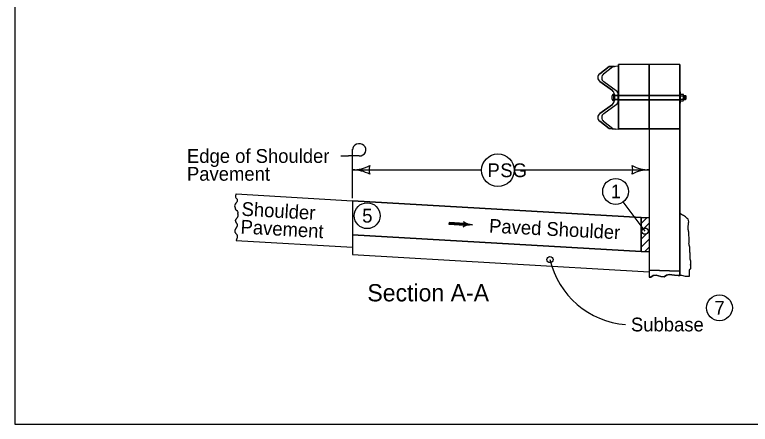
# Model space of a CAD drawing. Extents: x 6410 to 81668, y 3928 to 11667.
# Drawn here: x 6410 to 7264, y 8314 to 8790 of the extents above; entities that cross this region are included whole.
import ezdxf

# ---------------------------------------------------------------- set-up
doc = ezdxf.new("R2010")
doc.units = 0
for name, color, linetype in [('dsnNonPlotable', 7, 'Continuous'), ('dsnStdBlockModified', 7, 'Continuous'), ('dsnStdLabel', 7, 'Continuous'), ('dsnStdSection', 7, 'Continuous'), ('Level 11', 7, 'Continuous'), ('Level 14', 7, 'Continuous'), ('Level 3', 7, 'Continuous'), ('Level 7', 7, 'Continuous')]:
    doc.layers.add(name, color=color, linetype=linetype)

msp = doc.modelspace()

# ---------------------------------------------------------------- linework, layer by layer
at = {"layer": 'dsnNonPlotable'}
for p, q in [((6410.45, 9924.36), (6410.45, 8314.36)), ((6410.45, 8314.36), (9506.14, 8314.36))]:
    msp.add_line(p, q, dxfattribs=at)
at = {"layer": 'dsnStdBlockModified'}
for p, q in [((7182.32, 8731.84), (7111.23, 8731.84)), ((7111.23, 8657.19), (7111.23, 8731.84)), ((7146.78, 8657.19), (7146.78, 8731.84)), ((7182.32, 8731.84), (7182.32, 8486.8)), ((7089.29, 8721.08), (7100.05, 8729.48)), ((7093.72, 8720.85), (7104.5, 8729.26)), ((7100.05, 8729.48), (7106.38, 8729.59)), ((7104.5, 8729.26), (7110.83, 8730.38)), ((7103.99, 8701.54), (7089.48, 8711.96)), ((7108.47, 8701.31), (7093.9, 8711.76)), ((7105.62, 8689.44), (7105.62, 8697.52)), ((7182.32, 8700.14), (7183, 8700.14)), ((7183, 8686.8), (7183, 8700.14)), ((7105.62, 8695.83), (7111.04, 8695.83)), ((7105.62, 8691.17), (7111.23, 8691.17)), ((7106.39, 8690.1), (7106.39, 8696.91)), ((7106.39, 8690.1), (7106.39, 8693.51)), ((7106.39, 8693.51), (7106.39, 8690.1)), ((7106.56, 8695.83), (7111.23, 8695.83)), ((7110.83, 8693.29), (7110.83, 8696.69)), ((7110.83, 8689.88), (7110.83, 8693.29)), ((7110.83, 8693.29), (7110.83, 8689.88)), ((7111.22, 8690.83), (7182.32, 8690.83)), ((7111.23, 8696.17), (7182.32, 8696.17)), ((7111.23, 8695.83), (7182.32, 8695.83)), ((7111.23, 8691.17), (7182.32, 8691.17)), ((7183, 8697.51), (7185.97, 8697.51)), ((7183, 8695.49), (7185.97, 8695.49)), ((7183, 8691.45), (7185.97, 8691.45)), ((7183, 8689.43), (7185.97, 8689.43)), ((7186.34, 8690.44), (7186.34, 8696.5)), ((7186.34, 8695.8), (7188.71, 8695.8)), ((7186.34, 8691.14), (7188.71, 8691.14)), ((7187.23, 8695.8), (7187.23, 8691.14)), ((7187.97, 8695.8), (7187.97, 8691.14)), ((7188.71, 8695.8), (7189.15, 8695.27)), ((7188.71, 8695.8), (7188.71, 8691.14)), ((7189.15, 8691.67), (7188.71, 8691.14)), ((7189.15, 8695.27), (7189.15, 8691.67)), ((7089.48, 8675.05), (7103.99, 8685.47)), ((7093.9, 8674.82), (7108.47, 8685.27)), ((7182.32, 8686.8), (7183, 8686.8)), ((7100.05, 8657.54), (7089.29, 8665.93)), ((7104.5, 8657.32), (7093.72, 8665.73)), ((7107.16, 8656.85), (7100.05, 8657.54)), ((7110.83, 8656.2), (7104.5, 8657.32)), ((7146.78, 8657.19), (7111.23, 8657.19)), ((7146.78, 8657.19), (7146.78, 8484.96)), ((6667.24, 8581.57), (6802.39, 8573.71)), ((6802.39, 8573.71), (6802.39, 8519.7)), ((6802.39, 8573.71), (7137.52, 8554.23)), ((7137.52, 8547.48), (7144.27, 8554.23)), ((7137.52, 8547.48), (7144.27, 8554.23)), ((7137.52, 8547.48), (7144.27, 8554.23)), ((7137.52, 8547.48), (7144.27, 8554.23)), ((7137.52, 8554.23), (7146.76, 8554.23)), ((7137.52, 8554.23), (7137.52, 8514.8)), ((7137.52, 8538.3), (7146.76, 8547.53)), ((7137.52, 8538.3), (7146.76, 8547.53)), ((7137.52, 8538.3), (7146.76, 8547.53)), ((7137.52, 8538.3), (7146.76, 8547.53)), ((7192.37, 8547.46), (7192.37, 8547.46)), ((7137.52, 8529.07), (7146.76, 8538.31)), ((7137.52, 8529.07), (7146.76, 8538.31)), ((7137.52, 8529.07), (7146.76, 8538.31)), ((7137.52, 8529.07), (7146.76, 8538.31)), ((6667.28, 8527.56), (6802.39, 8519.7)), ((7137.52, 8514.8), (6802.39, 8534.12)), ((7137.52, 8519.84), (7146.76, 8529.08)), ((6802.39, 8519.7), (6802.39, 8511.28)), ((7141.62, 8514.8), (7146.76, 8519.94)), ((6802.39, 8511.28), (7146.78, 8491.42)), ((7137.52, 8514.8), (7146.76, 8514.8))]:
    msp.add_line(p, q, dxfattribs=at)
for points in [[(7186.32, 8690.76), (7186.28, 8691.03), (7186.23, 8691.2), (7186.14, 8691.36), (7186.02, 8691.45), (7186.1, 8691.55), (7186.18, 8691.77), (7186.24, 8692.08), (7186.32, 8692.83), (7186.32, 8690.76), (7186.3, 8690.9), (7186.26, 8691.12), (7186.18, 8691.33), (7186.07, 8691.44), (7186.1, 8691.53), (7186.16, 8691.68), (7186.27, 8692.18), (7186.31, 8692.56), (7186.3, 8690.95), (7186.28, 8691.07), (7186.23, 8691.24), (7186.1, 8691.44), (7186.16, 8691.61), (7186.23, 8691.94), (7186.29, 8692.27), (7186.28, 8691.11), (7186.24, 8691.24), (7186.13, 8691.43), (7186.17, 8691.65), (7186.23, 8691.9), (7186.27, 8692.08), (7186.26, 8691.21), (7186.2, 8691.32), (7186.16, 8691.43), (7186.24, 8691.89), (7186.24, 8691.29), (7186.17, 8691.43), (7186.22, 8691.72), (7186.22, 8691.37), (7186.19, 8691.44), (7186.2, 8691.54), (7186.2, 8691.46)], [(7186.03, 8695.49), (7186.11, 8695.54), (7186.18, 8695.64), (7186.26, 8695.86), (7186.32, 8696.15), (7186.32, 8694.2), (7186.26, 8694.71), (7186.21, 8695.08), (7186.09, 8695.41), (7186.04, 8695.49), (7186.09, 8695.5), (7186.2, 8695.65), (7186.28, 8695.87), (7186.3, 8696.03), (7186.31, 8694.49), (7186.23, 8694.98), (7186.18, 8695.25), (7186.07, 8695.47), (7186.1, 8695.48), (7186.24, 8695.7), (7186.28, 8695.85), (7186.29, 8694.75), (7186.1, 8695.46), (7186.26, 8695.74), (7186.27, 8694.88), (7186.12, 8695.45), (7186.24, 8695.67), (7186.25, 8695.03), (7186.14, 8695.43), (7186.23, 8695.6), (7186.23, 8695.19), (7186.16, 8695.42), (7186.21, 8695.53), (7186.21, 8695.33), (7186.18, 8695.4), (7186.19, 8695.45)], [(7192.84, 8523.62), (7192.78, 8523.35), (7192.78, 8523.15), (7192.78, 8522.95), (7192.78, 8522.76), (7192.78, 8522.56), (7192.78, 8522.37), (7192.78, 8522.08), (7192.78, 8521.88), (7192.88, 8521.59), (7192.98, 8521.29), (7193.17, 8521.1), (7193.17, 8520.9), (7193.27, 8520.71), (7193.27, 8520.51), (7193.27, 8520.32), (7193.37, 8520.22), (7193.37, 8520.02), (7193.37, 8519.83), (7193.37, 8519.63), (7193.37, 8519.44), (7193.37, 8519.24), (7193.37, 8518.95), (7193.37, 8518.66), (7193.37, 8518.46), (7193.37, 8518.17), (7193.37, 8517.97), (7193.37, 8517.78), (7193.47, 8517.68), (7193.47, 8517.48), (7193.47, 8517.29), (7193.47, 8517.09), (7193.47, 8516.9), (7193.47, 8516.7), (7193.47, 8516.51), (7193.47, 8516.31), (7193.47, 8516.12), (7193.47, 8515.92), (7193.47, 8515.72), (7193.47, 8515.53), (7193.47, 8515.33), (7193.47, 8515.14), (7193.47, 8514.94), (7193.47, 8514.75), (7193.47, 8514.55), (7193.47, 8514.36), (7193.47, 8514.16), (7193.57, 8514.06), (7193.57, 8513.87), (7193.57, 8513.67), (7193.66, 8513.57), (7193.66, 8513.38), (7193.66, 8513.18), (7193.76, 8513.09), (7193.76, 8512.89), (7193.76, 8512.7), (7193.76, 8512.5), (7193.76, 8512.21), (7193.86, 8511.91), (7193.86, 8511.72), (7193.86, 8511.52), (7193.86, 8511.33), (7193.86, 8511.13), (7193.86, 8510.94), (7193.86, 8510.74), (7193.86, 8510.55), (7193.86, 8510.35), (7193.86, 8510.16), (7193.86, 8509.96), (7193.86, 8509.76), (7193.86, 8509.57), (7193.86, 8509.37), (7193.86, 8509.18), (7193.86, 8508.98), (7193.86, 8508.79), (7193.86, 8508.59), (7193.86, 8508.4), (7193.86, 8508.2), (7193.86, 8508.01), (7193.86, 8507.81), (7193.86, 8507.61), (7193.86, 8507.42), (7193.86, 8507.22), (7193.86, 8507.03), (7193.86, 8506.83), (7193.86, 8506.64), (7193.86, 8506.44), (7193.86, 8506.25), (7193.96, 8506.15), (7193.96, 8505.86), (7193.96, 8505.66), (7194.05, 8505.47), (7194.15, 8505.17), (7194.15, 8504.98), (7194.25, 8504.88), (7194.25, 8504.68), (7194.35, 8504.59), (7194.44, 8504.49), (7194.44, 8504.29), (7194.44, 8504.1), (7194.44, 8503.9), (7194.54, 8503.8), (7194.54, 8503.61), (7194.54, 8503.41), (7194.54, 8503.22), (7194.54, 8503.02), (7194.54, 8502.83), (7194.54, 8502.63), (7194.54, 8502.44), (7194.54, 8502.24), (7194.54, 8502.05), (7194.54, 8501.85), (7194.54, 8501.65), (7194.54, 8501.46), (7194.54, 8501.26), (7194.54, 8501.07), (7194.54, 8500.87), (7194.54, 8500.68), (7194.54, 8500.48), (7194.54, 8500.29), (7194.54, 8500.09), (7194.54, 8499.9), (7194.54, 8499.7), (7194.54, 8499.51), (7194.54, 8499.31), (7194.54, 8499.11), (7194.54, 8498.92), (7194.54, 8498.92), (7194.54, 8499.21), (7194.54, 8499.41), (7194.54, 8499.6), (7194.54, 8499.41), (7194.54, 8499.21), (7194.54, 8499.02), (7194.54, 8498.82), (7194.54, 8498.63), (7194.54, 8498.43), (7194.54, 8498.24), (7194.54, 8498.04), (7194.54, 8497.84), (7194.54, 8497.65), (7194.54, 8497.45), (7194.54, 8497.26), (7194.54, 8497.06), (7194.54, 8496.87), (7194.54, 8496.67), (7194.44, 8496.57), (7194.44, 8496.38), (7194.44, 8496.18), (7194.44, 8495.99), (7194.44, 8495.79), (7194.44, 8495.6), (7194.44, 8495.4), (7194.44, 8495.21), (7194.44, 8495.01), (7194.44, 8494.82), (7194.44, 8494.62), (7194.35, 8494.52), (7194.25, 8494.33), (7194.15, 8494.23), (7194.05, 8494.13), (7193.96, 8494.03), (7193.76, 8493.94), (7193.57, 8493.94), (7193.47, 8493.84), (7193.37, 8493.74), (7193.27, 8493.64), (7193.08, 8493.55), (7192.98, 8493.45), (7192.98, 8493.25), (7192.88, 8493.15), (7192.88, 8492.96), (7192.88, 8492.76), (7192.88, 8492.57), (7192.88, 8485.75)], [(7193.01, 8485.75), (7188.86, 8485.63), (7184.73, 8486.8), (7180.17, 8486.8), (7175.93, 8487.22), (7169.68, 8487.96), (7166.61, 8487.33), (7163.96, 8485.53), (7160.25, 8485.74), (7154.63, 8487.33), (7151.34, 8486.8), (7148.59, 8485.21), (7146.78, 8484.96)]]:
    msp.add_lwpolyline(points, dxfattribs=at)
for centre, radius, start, end in [((7092.76, 8716.59), 5.68, 127.75002, 234.69086), ((7097.21, 8716.37), 5.68, 127.75002, 234.69086), ((7107.69, 8693.49), 4.54, 117.20289, 242.8461), ((7100.71, 8696.91), 5.68, 360, 54.69099), ((7105.16, 8696.69), 5.68, 360, 54.69099), ((7100.71, 8690.1), 5.68, 305.30901, 0), ((7105.16, 8689.88), 5.68, 305.30901, 0), ((7092.76, 8670.42), 5.68, 125.30914, 232.24998), ((7097.21, 8670.2), 5.68, 125.30914, 232.24998)]:
    msp.add_arc(centre, radius, start, end, dxfattribs=at)
for centre in [(7185.97, 8696.5), (7185.97, 8690.44)]:
    msp.add_ellipse(centre, major_axis=(0, -1.01), ratio=0.362258, start_param=6.283156, end_param=9.424748, dxfattribs=at)
for points in [[(6667.24, 8581.57), (6666.74, 8577.97), (6667.78, 8576.47), (6668.65, 8574.17), (6668.04, 8572.11), (6666.13, 8569.73), (6665.62, 8567.83), (6666.13, 8565.54), (6667, 8563.16), (6668.04, 8562.45), (6669.43, 8559.91), (6669.42, 8559.07)], [(6667.45, 8541.96), (6667.67, 8542.21), (6667.86, 8542.47), (6668.22, 8543.03), (6668.5, 8543.62), (6668.61, 8543.93), (6668.71, 8544.24), (6668.85, 8544.86), (6668.89, 8545.48), (6668.85, 8546.07), (6668.79, 8546.35), (6668.75, 8546.48), (6668.71, 8546.61), (6668.5, 8546.99), (6668.21, 8547.35), (6667.92, 8547.72), (6667.67, 8548.12), (6667.53, 8548.4), (6667.39, 8548.68), (6667.13, 8549.26), (6666.93, 8549.82), (6666.85, 8550.12), (6666.8, 8550.41), (6666.79, 8550.54), (6666.79, 8550.67), (6666.94, 8551.44), (6667.15, 8551.96), (6667.41, 8552.47), (6667.85, 8553.11), (6668.37, 8553.65), (6668.88, 8554.2), (6669.11, 8554.51), (6669.31, 8554.85), (6669.52, 8555.32), (6669.67, 8555.8), (6669.78, 8556.27), (6669.81, 8556.51), (6669.82, 8556.63), (6669.83, 8556.75), (6669.79, 8557.26), (6669.63, 8557.77), (6669.58, 8557.9), (6669.53, 8558.03), (6669.48, 8558.15), (6669.46, 8558.29), (6669.42, 8559.07)], [(7192.84, 8523.62), (7193.16, 8526.52), (7192.94, 8531.39), (7192.5, 8537.14), (7191.84, 8541.56), (7192.06, 8544.88), (7192.5, 8549.08), (7191.84, 8552.17), (7189.63, 8554.16), (7187.64, 8555.93), (7185.42, 8557.04), (7183.21, 8558.36), (7182.33, 8559.03)], [(6667.45, 8541.96), (6667.24, 8541.73), (6666.99, 8541.49), (6666.76, 8541.25), (6666.58, 8540.98), (6666.44, 8540.7), (6666.3, 8540.41), (6666.04, 8539.84), (6665.92, 8539.56), (6665.83, 8539.27), (6665.76, 8538.98), (6665.73, 8538.83), (6665.71, 8538.68), (6665.72, 8538.17), (6665.85, 8537.65), (6666.06, 8537.14), (6666.32, 8536.63), (6666.76, 8535.99), (6667.28, 8535.44), (6667.79, 8534.9), (6668.02, 8534.59), (6668.22, 8534.25), (6668.62, 8533.3), (6668.73, 8532.83), (6668.74, 8532.35), (6668.71, 8532.06), (6668.66, 8531.77), (6668.6, 8531.49), (6668.54, 8531.2), (6668.22, 8530.05), (6668.04, 8529.44), (6667.85, 8528.84), (6667.62, 8528.25), (6667.5, 8527.96), (6667.36, 8527.68), (6667.28, 8527.56)]]:
    msp.add_spline(points, degree=3, dxfattribs=at)
at = {"layer": 'dsnStdLabel'}
msp.add_circle((6819.43, 8556.33), 15, dxfattribs=at)
at = {"layer": 'dsnStdSection'}
for p, q in [((6802.39, 8612.79), (6802.39, 8633.65)), ((6789.02, 8625.64), (6797.7, 8625.64)), ((6810.2, 8625.64), (6797.7, 8625.64)), ((6802.39, 8576.86), (6802.39, 8612.79)), ((6802.38, 8609.47), (6952.22, 8609.47)), ((6990.07, 8609.63), (7146.78, 8609.63)), ((6932.59, 8546.37), (6914.38, 8547.42)), ((6932.49, 8545.43), (6932.49, 8545.43)), ((6932.6, 8547.37), (6932.6, 8547.37))]:
    msp.add_line(p, q, dxfattribs=at)
for points in [[(6932.62, 8547.31), (6914.45, 8548.36), (6914.32, 8546.48), (6932.49, 8545.43), (6932.54, 8547.04), (6914.67, 8548.14), (6914.61, 8546.64), (6932.1, 8545.69), (6932.23, 8546.81), (6914.9, 8547.87), (6914.88, 8546.87), (6931.89, 8545.89), (6931.98, 8546.59), (6915.09, 8547.65), (6915.08, 8547.09), (6931.68, 8546.15)], [(6932.21, 8548.56), (6932.91, 8547.4), (6932.88, 8545.75), (6932.13, 8544.35), (6934.88, 8545.22), (6938.08, 8545.87), (6938.97, 8546), (6936.73, 8546.55), (6933.5, 8547.78), (6932.56, 8548.31), (6932.68, 8544.8), (6937.63, 8546.02), (6932.99, 8547.6), (6933, 8545.18), (6936.4, 8546.11), (6933.4, 8546.97), (6933.17, 8545.59), (6935.33, 8546.09), (6933.74, 8546.6), (6933.6, 8545.94), (6934.39, 8546.1)]]:
    msp.add_lwpolyline(points, dxfattribs=at)
msp.add_circle((6971.14, 8609.07), 18.93, dxfattribs=at)
for centre, radius, start, end in [((6802.38, 8651.97), 42.5, 270, 298.07249), ((6838.02, 8609.47), 16.42, 162.26665, 197.73335), ((7111.14, 8609.63), 16.42, 342.26665, 17.73335), ((7146.78, 8652.13), 42.5, 241.92751, 270), ((6802.38, 8566.97), 42.5, 61.92751, 90), ((7146.78, 8567.13), 42.5, 90, 118.07249), ((7126.75, 8527.56), 97.76, 193.07698, 265.55799)]:
    msp.add_arc(centre, radius, start, end, dxfattribs=at)
for centre, major_axis, start_param, end_param in [((6810.2, 8632.78), (-7.81, 0), 1.570796, 6.283185), ((6928.82, 8546.58), (3.88, 0), 5.202895, 7.237436), ((6941.09, 8525.59), (22.17, 0), 1.537172, 2.061295), ((6943.88, 8566.01), (-22.17, 0), 0.954258, 1.478381)]:
    msp.add_ellipse(centre, major_axis=major_axis, ratio=0.913811, start_param=start_param, end_param=end_param, dxfattribs=at)
at = {"layer": 'Level 11'}
msp.add_line((7141.84, 8538.4), (7116.46, 8572.33), dxfattribs=at)
at = {"layer": 'Level 14'}
msp.add_circle((7031.52, 8505.44), 3.54, dxfattribs=at)
msp.add_circle((7031.52, 8505.44), 3.54, dxfattribs=at)
at = {"layer": 'Level 3'}
for p, q in [((7089.48, 8711.96), (7103.99, 8701.54)), ((7103.99, 8685.47), (7089.48, 8675.05)), ((7137.52, 8554.23), (6802.39, 8573.71)), ((6802.39, 8573.71), (6802.39, 8534.12)), ((7137.52, 8514.8), (7137.52, 8554.23)), ((6802.39, 8534.12), (7137.52, 8514.8))]:
    msp.add_line(p, q, dxfattribs=at)
for points in [[(7146.78, 8696.17), (7146.78, 8731.84), (7111.23, 8731.84), (7111.23, 8696.17), (7111.23, 8696.17), (7146.78, 8696.17)], [(7182.32, 8696.17), (7182.32, 8700.16), (7182.32, 8731.84), (7146.78, 8731.84), (7146.78, 8696.17), (7182.32, 8696.17)], [(7093.73, 8720.86), (7093.72, 8720.85), (7104.5, 8729.26), (7106.38, 8729.59), (7100.05, 8729.48), (7089.29, 8721.08)], [(7108.44, 8701.33), (7108.47, 8701.31), (7093.9, 8711.76), (7093.93, 8711.74)], [(7106.39, 8696.91), (7106.39, 8695.83), (7110.83, 8695.83), (7110.83, 8696.69), (7110.83, 8696.69)], [(7110.83, 8689.88), (7110.83, 8689.88), (7110.83, 8691.17), (7106.39, 8691.17), (7106.39, 8690.1), (7106.39, 8691.17), (7106.39, 8691.17), (7106.39, 8690.1)], [(7111.23, 8695.83), (7111.23, 8691.17), (7111.23, 8691.17), (7146.78, 8691.17), (7146.78, 8695.83), (7111.23, 8695.83), (7111.23, 8695.83)], [(7111.23, 8690.83), (7111.23, 8657.19), (7146.78, 8657.19), (7146.78, 8690.83), (7111.23, 8690.83)], [(7182.32, 8691.17), (7182.32, 8695.83), (7146.78, 8695.83), (7146.78, 8691.17), (7182.32, 8691.17)], [(7182.32, 8657.19), (7182.32, 8686.83), (7182.32, 8690.83), (7146.78, 8690.83), (7146.78, 8657.19), (7182.32, 8657.19)], [(7093.93, 8674.84), (7093.9, 8674.82), (7108.47, 8685.27), (7108.44, 8685.25)], [(7089.29, 8665.93), (7100.05, 8657.54), (7107.16, 8656.85), (7104.5, 8657.32), (7093.72, 8665.73), (7093.73, 8665.71)], [(7182.32, 8491.85), (7182.32, 8657.19), (7146.78, 8657.19), (7146.78, 8554.22), (7146.78, 8547.53), (7146.78, 8547.53), (7146.78, 8547.53), (7146.78, 8538.3), (7146.78, 8538.3), (7146.78, 8538.3), (7146.78, 8529.16), (7146.78, 8529.16), (7146.78, 8529.16), (7146.78, 8522.23), (7146.78, 8493.01), (7182.32, 8491.85)], [(7182.32, 8491.85), (7146.78, 8493.01), (7146.78, 8484.96), (7148.59, 8485.21), (7151.34, 8486.8), (7154.63, 8487.33), (7160.25, 8485.74), (7163.96, 8485.53), (7166.61, 8487.33), (7169.68, 8487.96), (7175.93, 8487.22), (7180.17, 8486.8), (7182.32, 8486.8), (7182.32, 8491.85)]]:
    msp.add_lwpolyline(points, dxfattribs=at)
msp.add_lwpolyline([(7110.83, 8695.83), (7106.39, 8695.83), (7106.39, 8692.37), (7106.39, 8693.51), (7106.39, 8691.17), (7110.83, 8691.17)], close=True, dxfattribs=at)
for centre, start, end in [((7092.76, 8716.59), 127.75002, 234.69086), ((7097.21, 8716.37), 127.75002, 234.69086), ((7100.71, 8696.91), 0, 54.69099), ((7105.16, 8696.69), 0, 54.69099), ((7100.71, 8690.1), 305.30901, 0), ((7105.16, 8689.88), 305.30901, 0), ((7092.76, 8670.42), 125.30914, 232.24998), ((7097.21, 8670.2), 125.30914, 232.24998)]:
    msp.add_arc(centre, 5.68, start, end, dxfattribs=at)
at = {"layer": 'Level 7'}
for centre, radius in [((7107.71, 8584.52), 15), ((6819.43, 8556.33), 15), ((7141.84, 8538.4), 3.58), ((7228.16, 8449.47), 15)]:
    msp.add_circle(centre, radius, dxfattribs=at)

# ---------------------------------------------------------------- texts
at = {"layer": 'dsnStdSection'}
for s, height, p in [('Edge of Shoulder ', 16, (6610.32, 8617.64)), ('Pavement', 16, (6610.32, 8596.93)), ('P', 16, (6959.02, 8601.07)), ('SG', 16, (6973.93, 8601.07)), ('Section A-A', 20, (6819.64, 8456.94)), ('Subbase', 16, (7125.53, 8422.09))]:
    msp.add_text(s, height=height, dxfattribs=at).set_placement(p)
for s, rotation, p in [('Shoulder', 356.73462, (6673.37, 8556.4)), ('Paved Shoulder ', 357.0678, (6960.6, 8536.73)), ('Pavement', 356.73462, (6672.19, 8535.73))]:
    msp.add_text(s, height=16, rotation=rotation, dxfattribs=at).set_placement(p)
at = {"layer": 'Level 7'}
for s, p in [('1', (7102.09, 8576.52)), ('5', (6813.67, 8548.33)), ('7', (7222.45, 8441.47))]:
    msp.add_text(s, height=16, dxfattribs=at).set_placement(p)

doc.saveas('drawing.dxf')
